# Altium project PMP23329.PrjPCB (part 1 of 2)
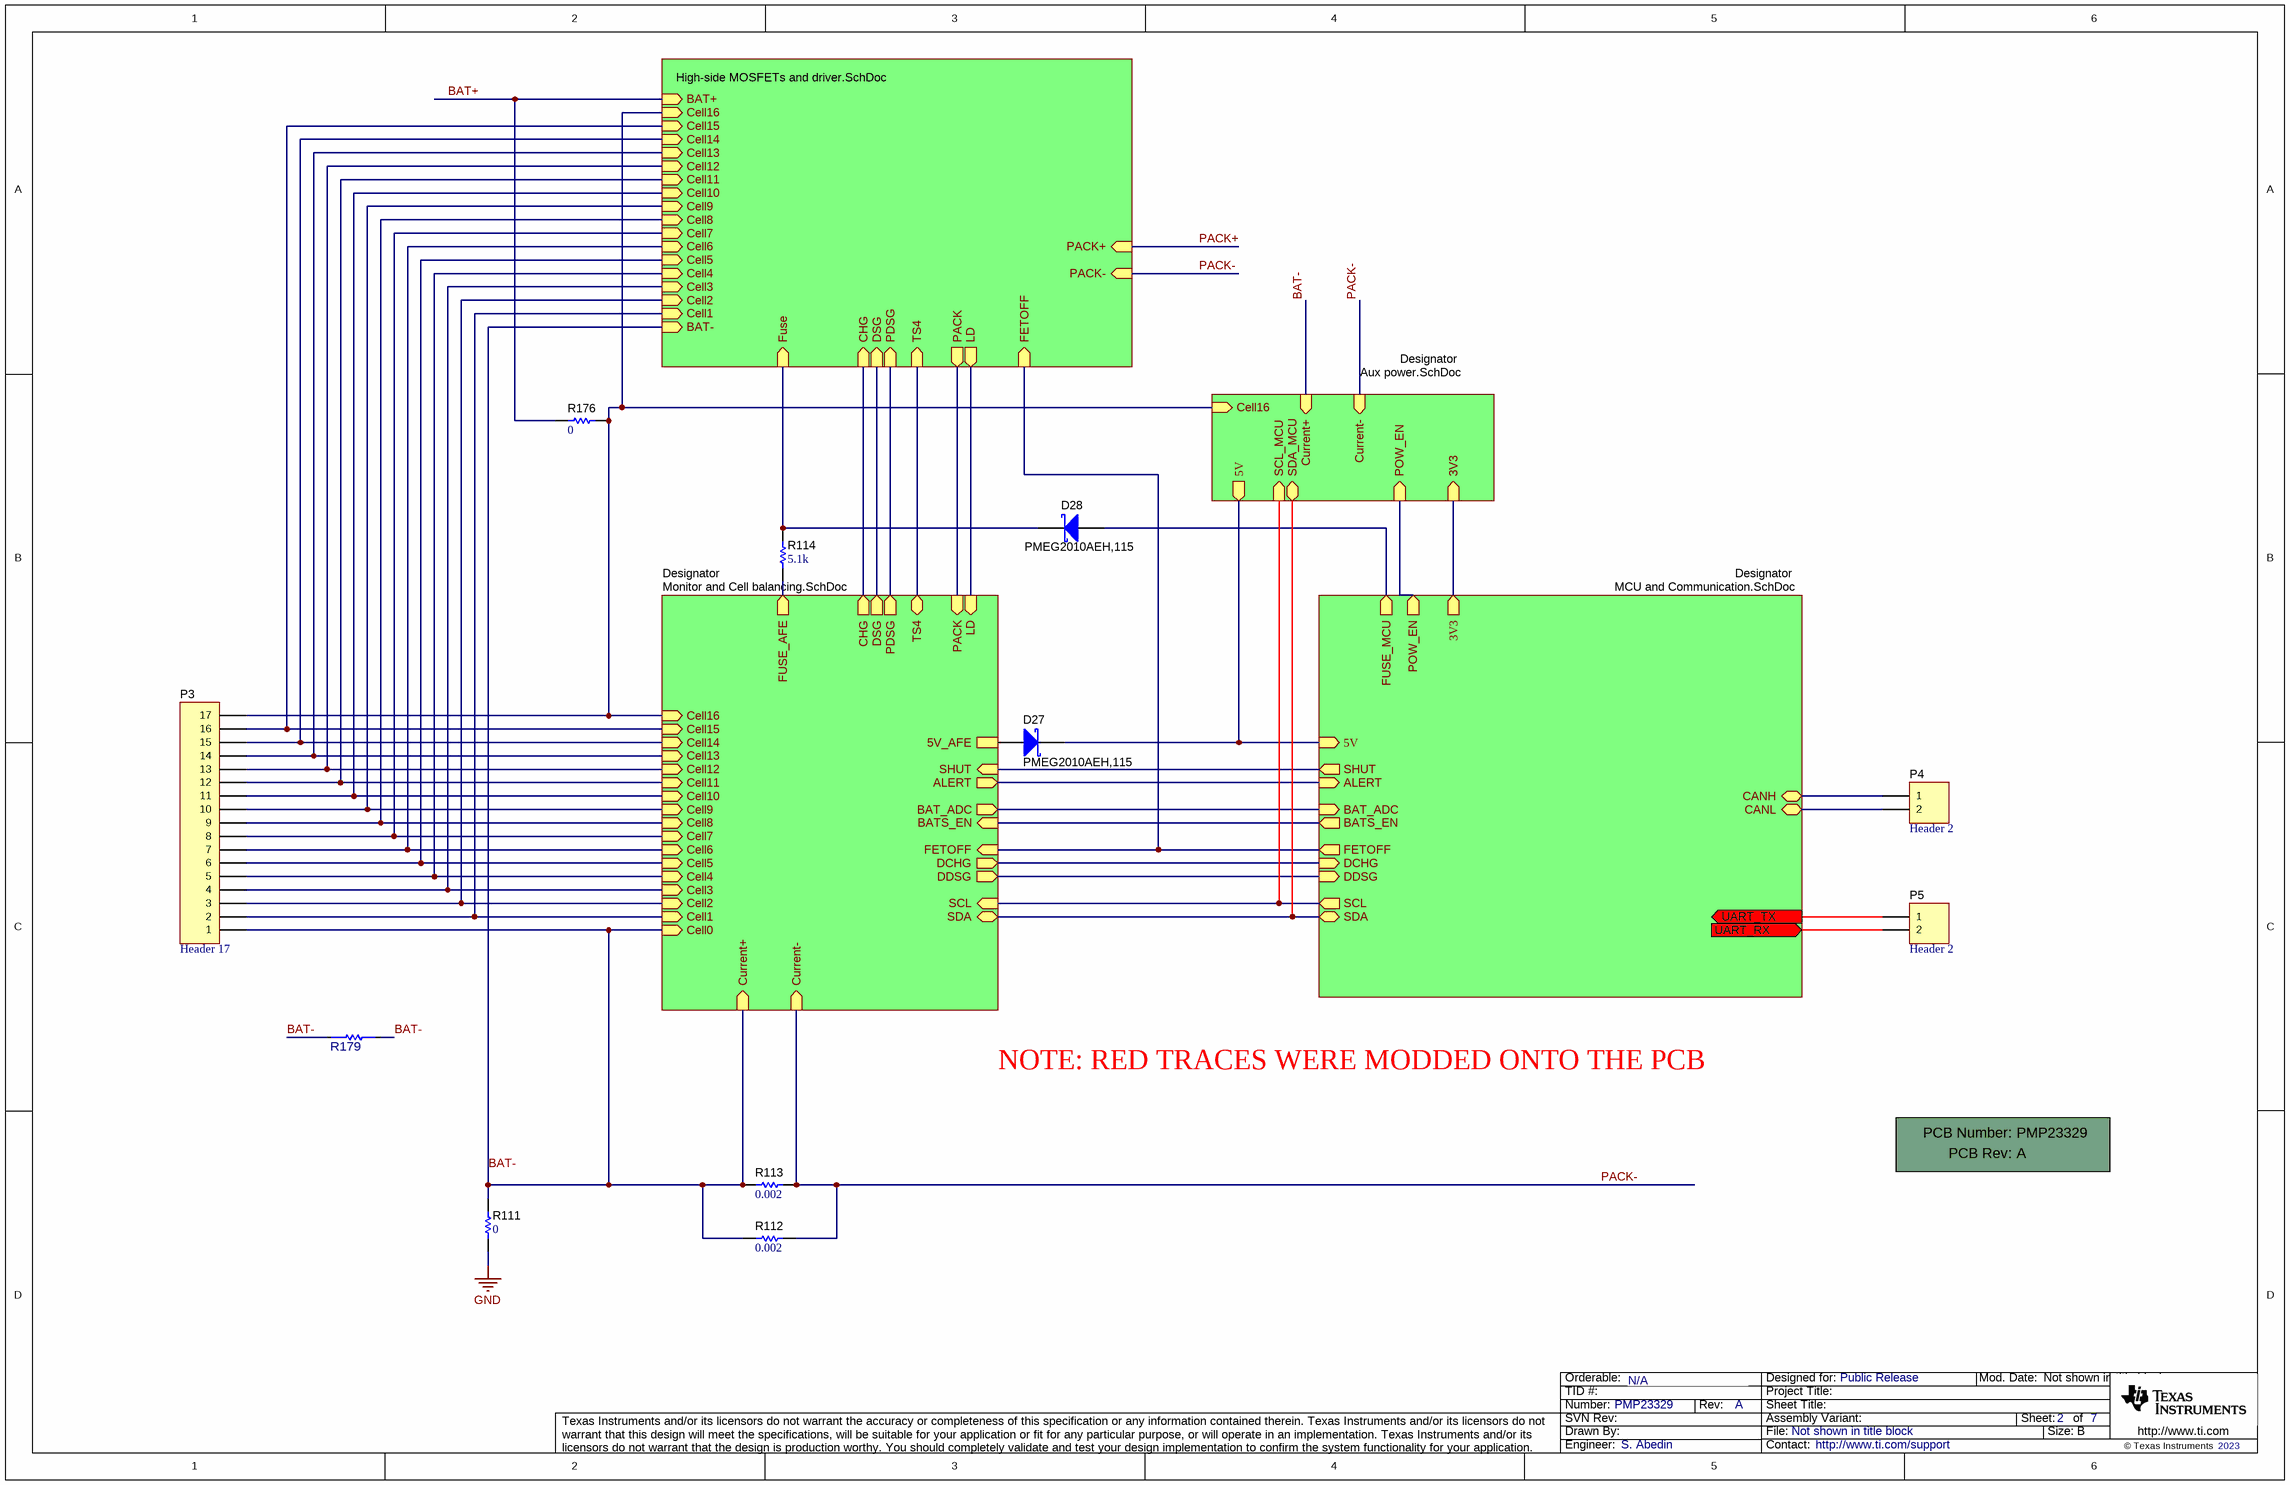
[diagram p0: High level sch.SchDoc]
CopyrightYear: 2023; PCB_Layout: S. Abedin; PCB_Rev: A; PRJ_Customer: Public Release; PRJ_Engineer: S. Abedin; PRJ_Number: PMP23329; SCH_Rev: A; TechSupport: http://www.ti.com/support
5 sheets, 381 parts. Net scope: hierarchical (ports join the sheet entries above them; power ports are global).
Board file: v1.PcbDoc
Sheets:
  High level sch.SchDoc
    Designator = Monitor and Cell balancing.SchDoc
    Designator = Aux power.SchDoc
    Designator = MCU and Communication.SchDoc
    Designator = High-side MOSFETs and driver.SchDoc

## Sheet High level sch.SchDoc
size 431 x 279 mm; Date: Not shown in title block; ApprovedBy: Not shown in title block; CheckedBy: Not shown in title block; Author: Not shown in title block; CompanyName: Not shown in title block; Engineer: Not shown in title block; Organization: Not shown in title block; Address1: Not shown in title block; Address2: Not shown in title block; Address3: Not shown in title block; Address4: Not shown in title block; DocumentNumber: 1; Revision: Use project parameter SCH_Rev; SheetNumber: 2; SheetTotal: 7; PageSetup: Record=PageOptions¦CenterHorizontal=True¦CenterVertical=True¦PrintScale=1.00¦XCorrection=1.00¦YCorrection=1.00¦PrintKind=0¦BorderSize=5000000¦LeftOffset=0¦BottomOffset=0¦Orientation=2¦PaperLength=1000¦PaperWidth=1000¦Scale=100¦PaperSource=15¦PrintQuality=600¦MediaType=1¦DitherType=10¦PaperKind=Letter¦PrintScaleMode=1

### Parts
!PCB1  Printed Circuit Board  (value not drawn)  (mechanical)
D27  PMEG2010AEH,115  [SOD-123F]
D28  PMEG2010AEH,115  [SOD-123F]
P3  Header 17  [HDR1X17]
P4  Header 2  [HDR1X2]
P5  Header 2  [HDR1X2]
R111  ValueDisplayed: 0  [1206]  (hidden comment: MCR18EZHJ000)
R112  ValueDisplayed: 0.002  [2512]  (hidden comment: CSNL2512FT2L00)
R113  ValueDisplayed: 0.002  [2512]  (hidden comment: CSNL2512FT2L00)
R114  ValueDisplayed: 5.1k  [0603S]  (hidden comment: CRCW06035K10JNEA)
R176  ValueDisplayed: 0  [2010]  (hidden comment: CRCW20100000Z0EF)
R179  RC2512FK-070RL  [FP-RC2512FK-070RL_2512-MFG]  (value not drawn)

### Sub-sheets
Designator = Monitor and Cell balancing.SchDoc: SHUT (in), ALERT (out), DDSG (out), DSG (out), DCHG (out), SCL (in), PDSG (out), Cell9 (in), SDA (bidir), CHG (out), Cell4 (in), Cell3 (in), Cell5 (in), Current+ (in), Current- (in), Cell8 (in), Cell12 (in), Cell6 (in), Cell7 (in), Cell10 (in), Cell11 (in), Cell2 (in), Cell1 (in), Cell15 (in), Cell16 (in), Cell0 (in), Cell13 (in), Cell14 (in), FETOFF (in), PACK (in), LD (in), 5V_AFE, FUSE_AFE (out), BAT_ADC (out), BATS_EN (in), TS4 (bidir)
Designator = Aux power.SchDoc: POW_EN (in), Cell16 (in), 5V (out), 3V3 (in), Current+ (in), Current- (in), SCL_MCU (in), SDA_MCU (bidir)
Designator = MCU and Communication.SchDoc: SDA (bidir), SCL (out), CANL (bidir), CANH (bidir), ALERT (in), POW_EN (out), DDSG (in), DCHG (in), SHUT (out), FETOFF (out), FUSE_MCU (out), BAT_ADC (in), BATS_EN (out), 5V (in), 3V3 (out)
Designator = High-side MOSFETs and driver.SchDoc: PACK- (in), CHG (in), DSG (in), Fuse (in), PACK+ (in), BAT+ (in), PACK (out), LD (out), PDSG (in), BAT- (in), Cell9 (in), Cell4 (in), Cell3 (in), Cell5 (in), Cell8 (in), Cell12 (in), Cell6 (in), Cell7 (in), Cell10 (in), Cell11 (in), Cell2 (in), Cell1 (in), Cell15 (in), Cell16 (in), Cell13 (in), Cell14 (in), FETOFF (in), TS4 (in)

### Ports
UART_RX (in), UART_TX (out)

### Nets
GND: R111.1
3V3: sheet Designator/3V3, sheet Designator/3V3
5V: D27.1(K) ; sheet Designator/5V, sheet Designator/5V
5V_AFE: D27.2(A) ; sheet Designator/5V_AFE
ALERT: sheet Designator/ALERT, sheet Designator/ALERT
BAT+: R176.1 ; sheet Designator/BAT+
BAT-: P3.1 R111.2 R112.1 R113.1 R179.1 R179.2 ; sheet Designator/Current+, sheet Designator/Cell0, sheet Designator/Current+, sheet Designator/BAT-
BAT_ADC: sheet Designator/BAT_ADC, sheet Designator/BAT_ADC
BATS_EN: sheet Designator/BATS_EN, sheet Designator/BATS_EN
CANH: P4.1 ; sheet Designator/CANH
CANL: P4.2 ; sheet Designator/CANL
Cell1: P3.2 ; sheet Designator/Cell1, sheet Designator/Cell1
Cell2: P3.3 ; sheet Designator/Cell2, sheet Designator/Cell2
Cell3: P3.4 ; sheet Designator/Cell3, sheet Designator/Cell3
Cell4: P3.5 ; sheet Designator/Cell4, sheet Designator/Cell4
Cell5: P3.6 ; sheet Designator/Cell5, sheet Designator/Cell5
Cell6: P3.7 ; sheet Designator/Cell6, sheet Designator/Cell6
Cell7: P3.8 ; sheet Designator/Cell7, sheet Designator/Cell7
Cell8: P3.9 ; sheet Designator/Cell8, sheet Designator/Cell8
Cell9: P3.10 ; sheet Designator/Cell9, sheet Designator/Cell9
Cell10: P3.11 ; sheet Designator/Cell10, sheet Designator/Cell10
Cell11: P3.12 ; sheet Designator/Cell11, sheet Designator/Cell11
Cell12: P3.13 ; sheet Designator/Cell12, sheet Designator/Cell12
Cell13: P3.14 ; sheet Designator/Cell13, sheet Designator/Cell13
Cell14: P3.15 ; sheet Designator/Cell14, sheet Designator/Cell14
Cell15: P3.16 ; sheet Designator/Cell15, sheet Designator/Cell15
Cell16: P3.17 R176.2 ; sheet Designator/Cell16, sheet Designator/Cell16, sheet Designator/Cell16
CHG: sheet Designator/CHG, sheet Designator/CHG
DCHG: sheet Designator/DCHG, sheet Designator/DCHG
DDSG: sheet Designator/DDSG, sheet Designator/DDSG
DSG: sheet Designator/DSG, sheet Designator/DSG
FETOFF: sheet Designator/FETOFF, sheet Designator/FETOFF, sheet Designator/FETOFF
Fuse: D28.1(K) R114.2 ; sheet Designator/Fuse
FUSE_AFE: R114.1 ; sheet Designator/FUSE_AFE
FUSE_MCU: D28.2(A) ; sheet Designator/FUSE_MCU
LD: sheet Designator/LD, sheet Designator/LD
PACK: sheet Designator/PACK, sheet Designator/PACK
PACK-: R112.2 R113.2 ; sheet Designator/Current-, sheet Designator/Current-, sheet Designator/PACK-
PDSG: sheet Designator/PDSG, sheet Designator/PDSG
POW_EN: sheet Designator/POW_EN, sheet Designator/POW_EN
SCL_MCU: sheet Designator/SCL, sheet Designator/SCL_MCU, sheet Designator/SCL
SDA_MCU: sheet Designator/SDA, sheet Designator/SDA_MCU, sheet Designator/SDA
SHUT: sheet Designator/SHUT, sheet Designator/SHUT
TS4: sheet Designator/TS4, sheet Designator/TS4
UART_RX: P5.2 ; port UART_RX
UART_TX: P5.1 ; port UART_TX

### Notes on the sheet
- NOTE: RED TRACES WERE MODDED ONTO THE PCB
- N/A

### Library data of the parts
!PCB1 = CMP-0003618-2: Manufacturer: Any; PartNumber: PMP23329
D27 D28 = CMP-0077033-2: Diode, Schottky, 20 V, 1 A, SOD-123F; Manufacturer: Nexperia; Vf_V: 430mV; Value: 20V; Value1: 1A; Value2: 0.43V; TJmax_C: 150°C; SizeAreaWB_mm2: 11.7; SizeArea_mm2: 5.6; SizeX_mm: 3.5; SizeY_mm: 1.6; SizeZ_mm: 1.1; AEC Category: Q101; Green_Lifecycle: Not Set; Green_REACh: Incomplete
P3 = Header 17: Header, 17-Pin
P4 P5 = Header 2: Header, 2-Pin
R111 = CMP-0018756-3: RES, 0, 5%, 0.25 W, 1206; Manufacturer: Rohm; SizeZ_mm: 1.35; SizeY_mm: 1.6; Value_Code: 0000; TempCo: 200 ppm/C; SizeArea_mm2: 5.12; U/M: EA; EIA_Code: E24; Value2: 0.25W; AEC Category: Q200; MFG_Status: TI_Obsolete; Value: 0; SizeX_mm: 3.2; VDC_V: 200V; Power_W: 250mW
R112 R113 = CMP-0015756-2: RES, 0.002, 1%, 2 W, 2512; Manufacturer: Stackpole Electronics Inc; Value: 0.002; Res_ohm: 2m; Value_Code: 2L000; Power_W: 2W; VDC_V: 200V; TempCo: 50 ppm/C; SizeArea_mm2: 20.16; SizeX_mm: 6.3; SizeY_mm: 3.2; SizeZ_mm: 0.71; U/M: EA; AEC Category: Q200
R114 = CMP-0025830-4: RES, 5.1 k, 5%, 0.1 W, AEC-Q200 Grade 0, 0603; Manufacturer: Vishay-Dale; Value: 5.1k; Value_Code: 5k10; Power_W: 100mW; Value2: 0.1W; VDC_V: 75V; TempCo: 200 ppm/C; SizeArea_mm2: 1.28; SizeX_mm: 1.6; SizeY_mm: 0.8; SizeZ_mm: 1; EIA_Code: E24; AEC Category: Q200; AEC Qualified: Y; AEC Grade: 0
R176 = CMP-0016044-2: RES, 0, 5%, 0.75 W, AEC-Q200 Grade 0, 2010; Manufacturer: Vishay-Dale; Power_W: 750mW; TempCo: ppm/C; Value_Code: 0000; U/M: EA; Value: 0; EIA_Code: E24; SizeX_mm: 5; SizeY_mm: 2.5; SizeZ_mm: 1.66; Value2: 0.75W; SizeArea_mm2: 12.5; AEC Qualified: Y; AEC Category: Q200
R179 = CMP-0096746-1: 0 Ohms Jumper 1W Chip Resistor 2512 (6432 Metric) Moisture Resistant Thick Film; Manufacturer: YAGEO; Value: 0; AEC Qualified: No; VDC_V: 200V; SizeZ_mm: 0.65mm; Max Current: 10A

## Sheet Monitor and Cell balancing.SchDoc
size A3; Date: Not shown in title block; ApprovedBy: Not shown in title block; CheckedBy: Not shown in title block; Author: Not shown in title block; CompanyName: Not shown in title block; Engineer: Not shown in title block; Organization: Not shown in title block; Address1: Not shown in title block; Address2: Not shown in title block; Address3: Not shown in title block; Address4: Not shown in title block; DocumentNumber: 1; Revision: Use project parameter SCH_Rev; SheetNumber: 3; SheetTotal: 7; PageSetup: Record=PageOptions¦CenterHorizontal=True¦CenterVertical=True¦PrintScale=1.00¦XCorrection=1.00¦YCorrection=1.00¦PrintKind=0¦BorderSize=5000000¦LeftOffset=0¦BottomOffset=0¦Orientation=2¦PaperLength=1000¦PaperWidth=1000¦Scale=100¦PaperSource=15¦PrintQuality=600¦MediaType=1¦DitherType=10¦PaperKind=Letter¦PrintScaleMode=1
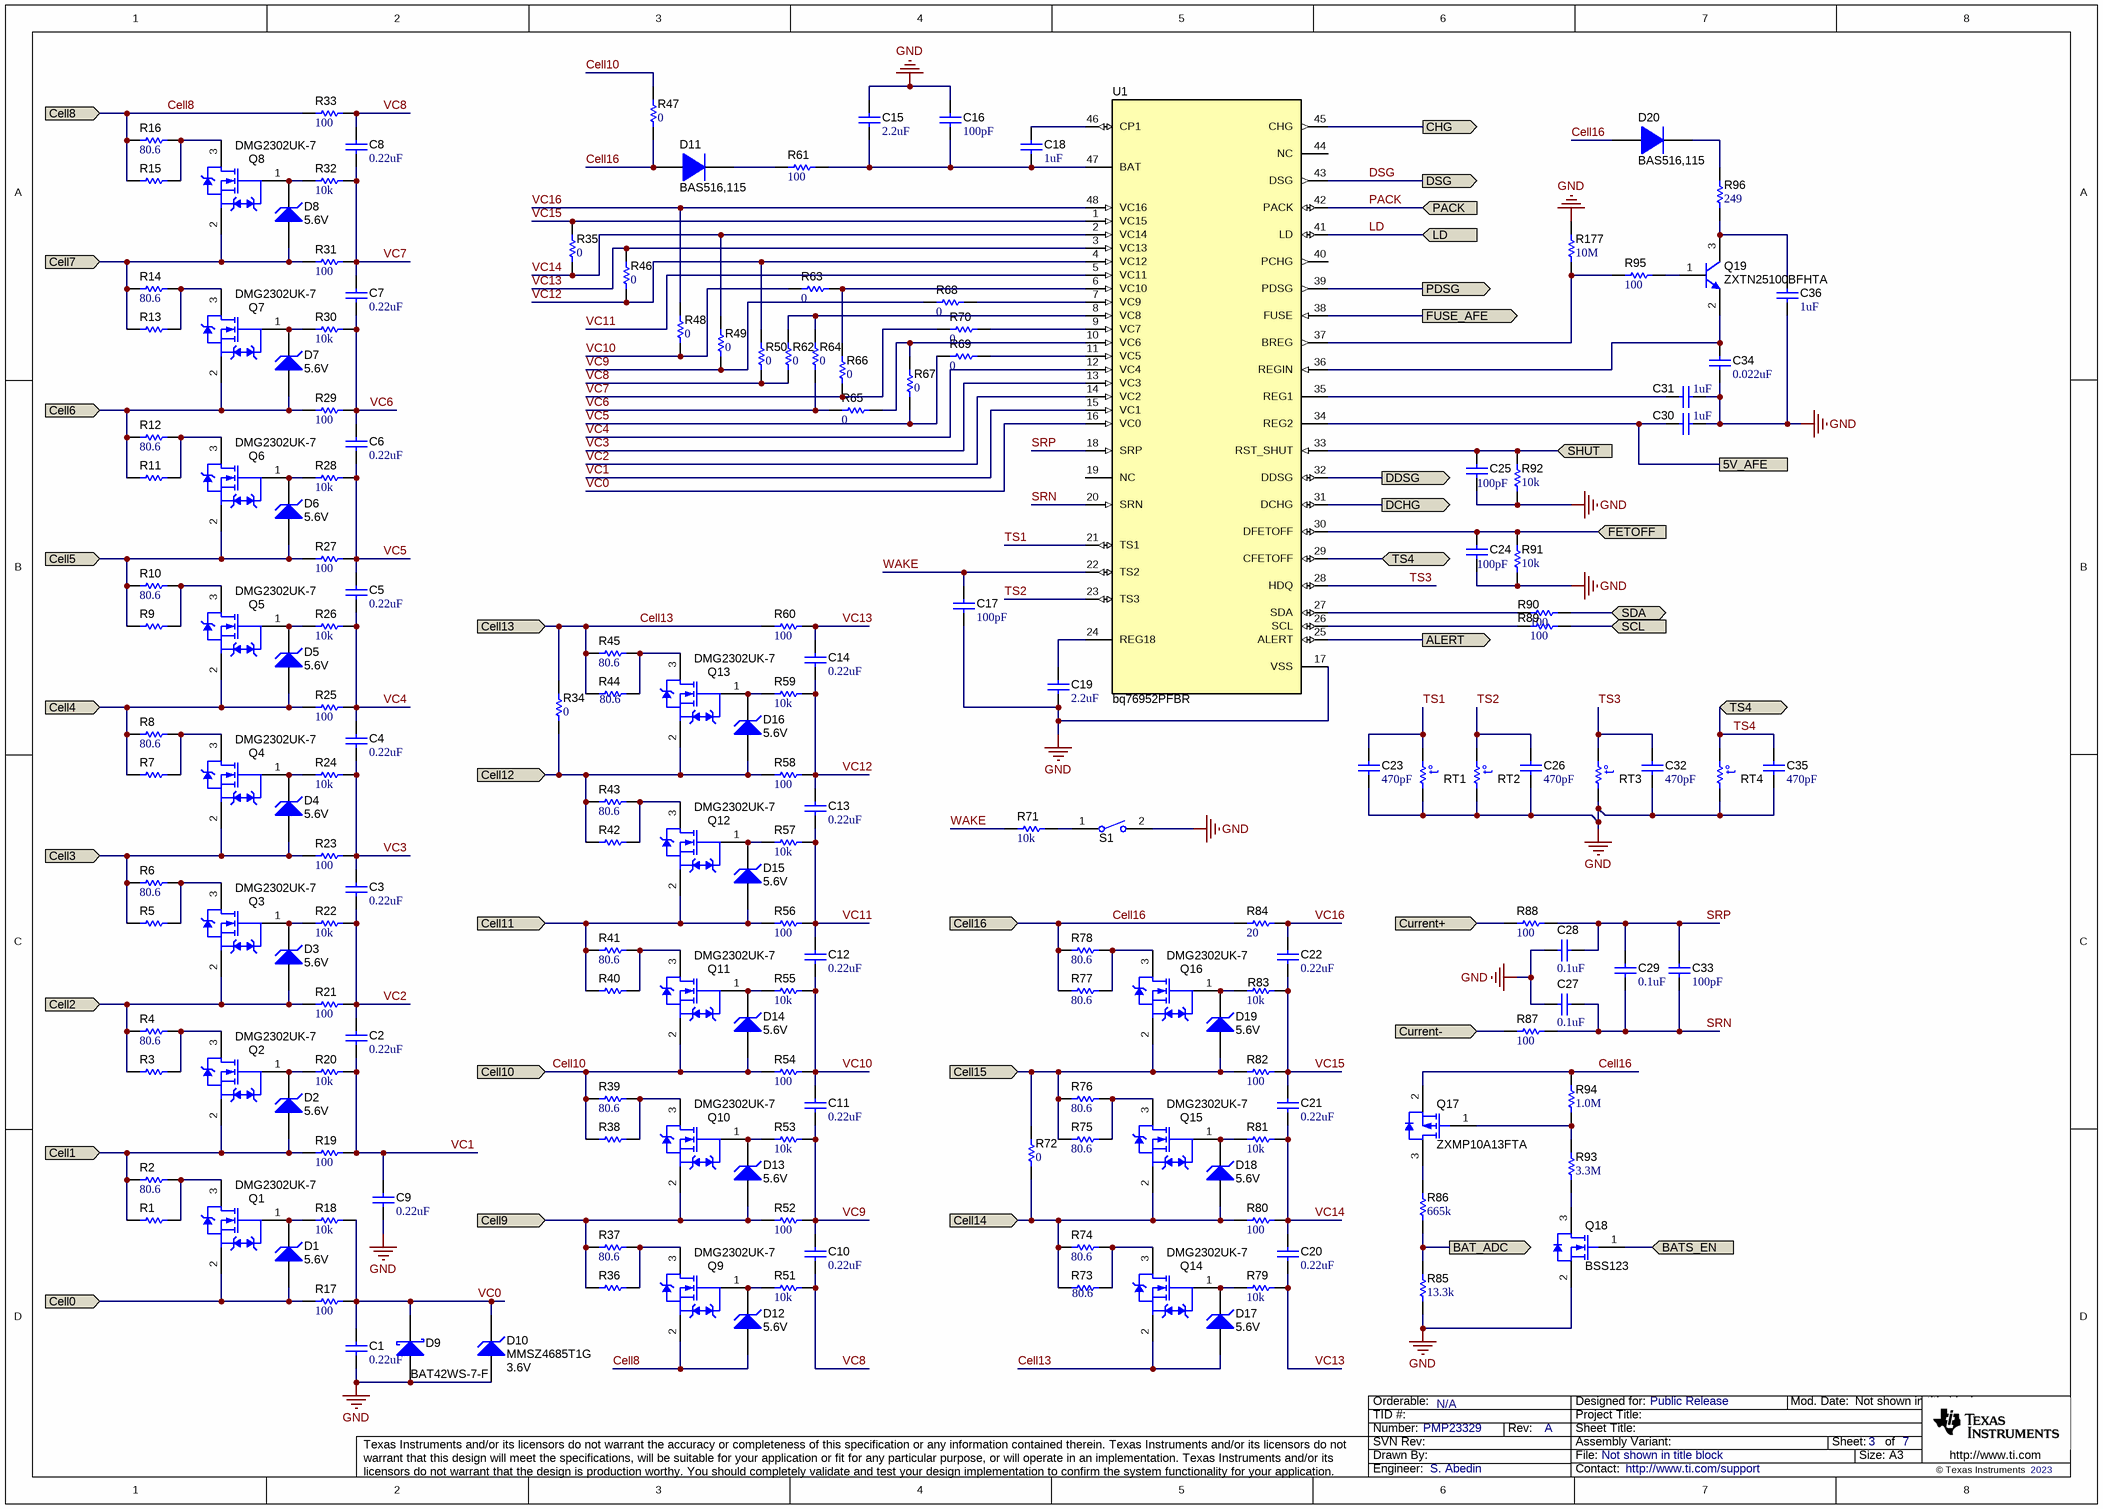
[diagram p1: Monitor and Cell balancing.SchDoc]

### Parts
C1  ValueDisplayed: 0.22uF  [0603S]  (hidden comment: GCM188R71H224KA64D)
C2  ValueDisplayed: 0.22uF  [0603S]  (hidden comment: GCM188R71H224KA64D)
C3  ValueDisplayed: 0.22uF  [0603S]  (hidden comment: GCM188R71H224KA64D)
C4  ValueDisplayed: 0.22uF  [0603S]  (hidden comment: GCM188R71H224KA64D)
C5  ValueDisplayed: 0.22uF  [0603S]  (hidden comment: GCM188R71H224KA64D)
C6  ValueDisplayed: 0.22uF  [0603S]  (hidden comment: GCM188R71H224KA64D)
C7  ValueDisplayed: 0.22uF  [0603S]  (hidden comment: GCM188R71H224KA64D)
C8  ValueDisplayed: 0.22uF  [0603S]  (hidden comment: GCM188R71H224KA64D)
C9  ValueDisplayed: 0.22uF  [0603S]  (hidden comment: GCM188R71H224KA64D)
C10  ValueDisplayed: 0.22uF  [0603S]  (hidden comment: GCM188R71H224KA64D)
C11  ValueDisplayed: 0.22uF  [0603S]  (hidden comment: GCM188R71H224KA64D)
C12  ValueDisplayed: 0.22uF  [0603S]  (hidden comment: GCM188R71H224KA64D)
C13  ValueDisplayed: 0.22uF  [0603S]  (hidden comment: GCM188R71H224KA64D)
C14  ValueDisplayed: 0.22uF  [0603S]  (hidden comment: GCM188R71H224KA64D)
C15  ValueDisplayed: 2.2uF  [1206_190]  (hidden comment: CL31B225KCHSNNE)
C16  ValueDisplayed: 100pF  [0603S]  (hidden comment: GRM1885C2A101JA01D)
C17  ValueDisplayed: 100pF  [0603S]  (hidden comment: GRM1885C2A101JA01D)
C18  ValueDisplayed: 1uF  [0603S]  (hidden comment: C1608X7R1E105K080AB)
C19  ValueDisplayed: 2.2uF  [0603S]  (hidden comment: EMK107BB7225MA-T)
C20  ValueDisplayed: 0.22uF  [0603S]  (hidden comment: GCM188R71H224KA64D)
C21  ValueDisplayed: 0.22uF  [0603S]  (hidden comment: GCM188R71H224KA64D)
C22  ValueDisplayed: 0.22uF  [0603S]  (hidden comment: GCM188R71H224KA64D)
C23  ValueDisplayed: 470pF  [0603S]  (hidden comment: GRM188R71H471KA01D)
C24  ValueDisplayed: 100pF  [0603S]  (hidden comment: GRM1885C2A101JA01D)
C25  ValueDisplayed: 100pF  [0603S]  (hidden comment: GRM1885C2A101JA01D)
C26  ValueDisplayed: 470pF  [0603S]  (hidden comment: GRM188R71H471KA01D)
C27  ValueDisplayed: 0.1uF  [0603S]  (hidden comment: GRM188R71H104KA93D)
C28  ValueDisplayed: 0.1uF  [0603S]  (hidden comment: GRM188R71H104KA93D)
C29  ValueDisplayed: 0.1uF  [0603S]  (hidden comment: GRM188R71H104KA93D)
C30  ValueDisplayed: 1uF  [0603S]  (hidden comment: GCM188R71C105KA64D)
C31  ValueDisplayed: 1uF  [0603S]  (hidden comment: GCM188R71C105KA64D)
C32  ValueDisplayed: 470pF  [0603S]  (hidden comment: GRM188R71H471KA01D)
C33  ValueDisplayed: 100pF  [0603S]  (hidden comment: GRM1885C2A101JA01D)
C34  ValueDisplayed: 0.022uF  [0603S]  (hidden comment: GRM188R71H223KA01D)
C35  ValueDisplayed: 470pF  [0603S]  (hidden comment: GRM188R71H471KA01D)
C36  ValueDisplayed: 1uF  [1206_180]  (hidden comment: C3216X7R2A105K160AA)
D1  value 5.6V  [SOD-523]  (hidden comment: BZT52C5V6T-7)
D2  value 5.6V  [SOD-523]  (hidden comment: BZT52C5V6T-7)
D3  value 5.6V  [SOD-523]  (hidden comment: BZT52C5V6T-7)
D4  value 5.6V  [SOD-523]  (hidden comment: BZT52C5V6T-7)
D5  value 5.6V  [SOD-523]  (hidden comment: BZT52C5V6T-7)
D6  value 5.6V  [SOD-523]  (hidden comment: BZT52C5V6T-7)
D7  value 5.6V  [SOD-523]  (hidden comment: BZT52C5V6T-7)
D8  value 5.6V  [SOD-523]  (hidden comment: BZT52C5V6T-7)
D9  BAT42WS-7-F  [SOD-323]
D10  MMSZ4685T1G  value 3.6V  [SOD-123]
D11  BAS516,115  [SOD-523]
D12  value 5.6V  [SOD-523]  (hidden comment: BZT52C5V6T-7)
D13  value 5.6V  [SOD-523]  (hidden comment: BZT52C5V6T-7)
D14  value 5.6V  [SOD-523]  (hidden comment: BZT52C5V6T-7)
D15  value 5.6V  [SOD-523]  (hidden comment: BZT52C5V6T-7)
D16  value 5.6V  [SOD-523]  (hidden comment: BZT52C5V6T-7)
D17  value 5.6V  [SOD-523]  (hidden comment: BZT52C5V6T-7)
D18  value 5.6V  [SOD-523]  (hidden comment: BZT52C5V6T-7)
D19  value 5.6V  [SOD-523]  (hidden comment: BZT52C5V6T-7)
D20  BAS516,115  [SOD-523]
Q1  DMG2302UK-7  [SOT-23]
Q2  DMG2302UK-7  [SOT-23]
Q3  DMG2302UK-7  [SOT-23]
Q4  DMG2302UK-7  [SOT-23]
Q5  DMG2302UK-7  [SOT-23]
Q6  DMG2302UK-7  [SOT-23]
Q7  DMG2302UK-7  [SOT-23]
Q8  DMG2302UK-7  [SOT-23]
Q9  DMG2302UK-7  [SOT-23]
Q10  DMG2302UK-7  [SOT-23]
Q11  DMG2302UK-7  [SOT-23]
Q12  DMG2302UK-7  [SOT-23]
Q13  DMG2302UK-7  [SOT-23]
Q14  DMG2302UK-7  [SOT-23]
Q15  DMG2302UK-7  [SOT-23]
Q16  DMG2302UK-7  [SOT-23]
Q17  ZXMP10A13FTA  [SOT-23]
Q18  BSS123  [SOT-23]
Q19  ZXTN25100BFHTA  [SOT-23]
R1  CRCW120680R6FKEA  [1206]  (value not drawn)
R2  ValueDisplayed: 80.6  [1206]  (hidden comment: CRCW120680R6FKEA)
R3  CRCW120680R6FKEA  [1206]  (value not drawn)
R4  ValueDisplayed: 80.6  [1206]  (hidden comment: CRCW120680R6FKEA)
R5  CRCW120680R6FKEA  [1206]  (value not drawn)
R6  ValueDisplayed: 80.6  [1206]  (hidden comment: CRCW120680R6FKEA)
R7  CRCW120680R6FKEA  [1206]  (value not drawn)
R8  ValueDisplayed: 80.6  [1206]  (hidden comment: CRCW120680R6FKEA)
R9  CRCW120680R6FKEA  [1206]  (value not drawn)
R10  ValueDisplayed: 80.6  [1206]  (hidden comment: CRCW120680R6FKEA)
R11  CRCW120680R6FKEA  [1206]  (value not drawn)
R12  ValueDisplayed: 80.6  [1206]  (hidden comment: CRCW120680R6FKEA)
R13  CRCW120680R6FKEA  [1206]  (value not drawn)
R14  ValueDisplayed: 80.6  [1206]  (hidden comment: CRCW120680R6FKEA)
R15  CRCW120680R6FKEA  [1206]  (value not drawn)
R16  ValueDisplayed: 80.6  [1206]  (hidden comment: CRCW120680R6FKEA)
R17  ValueDisplayed: 100  [0603S]  (hidden comment: CRCW0603100RFKEA)
R18  ValueDisplayed: 10k  [0603S]  (hidden comment: CRCW060310K0JNEA)
R19  ValueDisplayed: 100  [0603S]  (hidden comment: CRCW0603100RFKEA)
R20  ValueDisplayed: 10k  [0603S]  (hidden comment: CRCW060310K0JNEA)
R21  ValueDisplayed: 100  [0603S]  (hidden comment: CRCW0603100RFKEA)
R22  ValueDisplayed: 10k  [0603S]  (hidden comment: CRCW060310K0JNEA)
R23  ValueDisplayed: 100  [0603S]  (hidden comment: CRCW0603100RFKEA)
R24  ValueDisplayed: 10k  [0603S]  (hidden comment: CRCW060310K0JNEA)
R25  ValueDisplayed: 100  [0603S]  (hidden comment: CRCW0603100RFKEA)
R26  ValueDisplayed: 10k  [0603S]  (hidden comment: CRCW060310K0JNEA)
R27  ValueDisplayed: 100  [0603S]  (hidden comment: CRCW0603100RFKEA)
R28  ValueDisplayed: 10k  [0603S]  (hidden comment: CRCW060310K0JNEA)
R29  ValueDisplayed: 100  [0603S]  (hidden comment: CRCW0603100RFKEA)
R30  ValueDisplayed: 10k  [0603S]  (hidden comment: CRCW060310K0JNEA)
R31  ValueDisplayed: 100  [0603S]  (hidden comment: CRCW0603100RFKEA)
R32  ValueDisplayed: 10k  [0603S]  (hidden comment: CRCW060310K0JNEA)
R33  ValueDisplayed: 100  [0603S]  (hidden comment: CRCW0603100RFKEA)
R34  ValueDisplayed: 0  [0402]  (hidden comment: CRCW04020000Z0ED)
R35  ValueDisplayed: 0  [0603S]  (hidden comment: CRCW06030000Z0EA)
R36  CRCW120680R6FKEA  [1206]  (value not drawn)
R37  ValueDisplayed: 80.6  [1206]  (hidden comment: CRCW120680R6FKEA)
R38  CRCW120680R6FKEA  [1206]  (value not drawn)
R39  ValueDisplayed: 80.6  [1206]  (hidden comment: CRCW120680R6FKEA)
R40  CRCW120680R6FKEA  [1206]  (value not drawn)
R41  ValueDisplayed: 80.6  [1206]  (hidden comment: CRCW120680R6FKEA)
R42  CRCW120680R6FKEA  [1206]  (value not drawn)
R43  ValueDisplayed: 80.6  [1206]  (hidden comment: CRCW120680R6FKEA)
R44  value 80.6  [1206]  (hidden comment: CRCW120680R6FKEA)
R45  ValueDisplayed: 80.6  [1206]  (hidden comment: CRCW120680R6FKEA)
R46  ValueDisplayed: 0  [0402]  (hidden comment: CRCW04020000Z0ED)
R47  ValueDisplayed: 0  [0402]  (hidden comment: CRCW04020000Z0ED)
R48  ValueDisplayed: 0  [0603S]  (hidden comment: CRCW06030000Z0EA)
R49  ValueDisplayed: 0  [0603S]  (hidden comment: CRCW06030000Z0EA)
R50  ValueDisplayed: 0  [0603S]  (hidden comment: CRCW06030000Z0EA)
R51  ValueDisplayed: 10k  [0603S]  (hidden comment: CRCW060310K0JNEA)
R52  ValueDisplayed: 100  [0603S]  (hidden comment: CRCW0603100RFKEA)
R53  ValueDisplayed: 10k  [0603S]  (hidden comment: CRCW060310K0JNEA)
R54  ValueDisplayed: 100  [0603S]  (hidden comment: CRCW0603100RFKEA)
R55  ValueDisplayed: 10k  [0603S]  (hidden comment: CRCW060310K0JNEA)
R56  ValueDisplayed: 100  [0603S]  (hidden comment: CRCW0603100RFKEA)
R57  ValueDisplayed: 10k  [0603S]  (hidden comment: CRCW060310K0JNEA)
R58  ValueDisplayed: 100  [0603S]  (hidden comment: CRCW0603100RFKEA)
R59  ValueDisplayed: 10k  [0603S]  (hidden comment: CRCW060310K0JNEA)
R60  ValueDisplayed: 100  [0603S]  (hidden comment: CRCW0603100RFKEA)
R61  ValueDisplayed: 100  [0603S]  (hidden comment: CRCW0603100RFKEA)
R62  ValueDisplayed: 0  [0603S]  (hidden comment: CRCW06030000Z0EA)
R63  ValueDisplayed: 0  [0603S]  (hidden comment: CRCW06030000Z0EA)
R64  ValueDisplayed: 0  [0603S]  (hidden comment: CRCW06030000Z0EA)
R65  ValueDisplayed: 0  [0603S]  (hidden comment: CRCW06030000Z0EA)
R66  ValueDisplayed: 0  [0603S]  (hidden comment: CRCW06030000Z0EA)
R67  ValueDisplayed: 0  [0603S]  (hidden comment: CRCW06030000Z0EA)
R68  ValueDisplayed: 0  [0603S]  (hidden comment: CRCW06030000Z0EA)
R69  ValueDisplayed: 0  [0603S]  (hidden comment: CRCW06030000Z0EA)
R70  ValueDisplayed: 0  [0603S]  (hidden comment: CRCW06030000Z0EA)
R71  ValueDisplayed: 10k  [0603S]  (hidden comment: CRCW060310K0JNEA)
R72  ValueDisplayed: 0  [0402]  (hidden comment: CRCW04020000Z0ED)
R73  ValueDisplayed: 80.6  [1206]  (hidden comment: CRCW120680R6FKEA)
R74  ValueDisplayed: 80.6  [1206]  (hidden comment: CRCW120680R6FKEA)
R75  ValueDisplayed: 80.6  [1206]  (hidden comment: CRCW120680R6FKEA)
R76  ValueDisplayed: 80.6  [1206]  (hidden comment: CRCW120680R6FKEA)
R77  ValueDisplayed: 80.6  [1206]  (hidden comment: CRCW120680R6FKEA)
R78  ValueDisplayed: 80.6  [1206]  (hidden comment: CRCW120680R6FKEA)
R79  ValueDisplayed: 10k  [0603S]  (hidden comment: CRCW060310K0JNEA)
R80  ValueDisplayed: 100  [0603S]  (hidden comment: CRCW0603100RFKEA)
R81  ValueDisplayed: 10k  [0603S]  (hidden comment: CRCW060310K0JNEA)
R82  ValueDisplayed: 100  [0603S]  (hidden comment: CRCW0603100RFKEA)
R83  ValueDisplayed: 10k  [0603S]  (hidden comment: CRCW060310K0JNEA)
R84  ValueDisplayed: 20  [0603S]  (hidden comment: CRCW060320R0JNEA)
R85  ValueDisplayed: 13.3k  [0603S]  (hidden comment: RT0603DRE0713K3L)
R86  ValueDisplayed: 665k  [0603S]  (hidden comment: RT0603DRE07665KL)
R87  ValueDisplayed: 100  [0603S]  (hidden comment: CRCW0603100RFKEA)
R88  ValueDisplayed: 100  [0603S]  (hidden comment: CRCW0603100RFKEA)
R89  ValueDisplayed: 100  [0603S]  (hidden comment: CRCW0603100RFKEA)
R90  ValueDisplayed: 100  [0603S]  (hidden comment: CRCW0603100RFKEA)
R91  ValueDisplayed: 10k  [0603S]  (hidden comment: CRCW060310K0JNEA)
R92  ValueDisplayed: 10k  [0603S]  (hidden comment: CRCW060310K0JNEA)
R93  ValueDisplayed: 3.3M  [0603S]  (hidden comment: CRCW06033M30JNEA)
R94  ValueDisplayed: 1.0M  [0603S]  (hidden comment: CRCW06031M00JNEA)
R95  ValueDisplayed: 100  [0603S]  (hidden comment: CRCW0603100RFKEA)
R96  ValueDisplayed: 249  [0603S]  (hidden comment: RC0603FR-07249RL)
R177  ValueDisplayed: 10M  [0603S]  (hidden comment: CRCW060310M0JNEA)
RT1  MF51E103F3950  [Thermistor_103AT-2]  (value not drawn)
RT2  MF51E103F3950  [Thermistor_103AT-2]  (value not drawn)
RT3  MF51E103F3950  [Thermistor_103AT-2]  (value not drawn)
RT4  MF51E103F3950  [Thermistor_103AT-2]  (value not drawn)
S1  RS-032G05A3-SM RT  [SW_RS-032G05A3-SM]  (value not drawn)
U1  bq76952PFBR  [PFB0048A_N]

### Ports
5V_AFE, ALERT (out), BAT_ADC (out), BATS_EN (in), Cell0 (in), Cell1 (in), Cell2 (in), Cell3 (in), Cell4 (in), Cell5 (in), Cell6 (in), Cell7 (in), Cell8 (in), Cell9 (in), Cell10 (in), Cell11 (in), Cell12 (in), Cell13 (in), Cell14 (in), Cell15 (in), Cell16 (in), CHG (out), Current+ (in), Current- (in), DCHG (out), DDSG (out), DSG (out), FETOFF (in), FUSE_AFE (out), LD (in), PACK (in), PDSG (out), SCL (in), SDA (bidir), SHUT (in), TS4 (bidir)

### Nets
GND: C1.2 C9.2 C15.1 C16.1 C17.2 C19.2 C23.2 C24.2 C25.2 C26.2 C27.1 C28.1 C30.2 C31.2 C32.2 C34.2 C35.2 C36.2 D9.2(A) D10.2(A) Q18.2(S) R85.1 R91.1 R92.1 R177.2 RT1.1 RT2.1 RT3.1 RT4.1 S1.2 U1.17(VSS)
5V_AFE: C30.1 U1.34(REG2) ; port 5V_AFE
ALERT: U1.25(ALERT) ; port ALERT
BAT-: D1.2(A) Q1.2(S) R17.1 R88.1 ; port Cell0, port Current+
BAT_ADC: R85.2 R86.1 ; port BAT_ADC
BATS_EN: Q18.1(G) ; port BATS_EN
Cell1: D2.2(A) Q2.2(S) R1.1 R2.1 R19.1 ; port Cell1
Cell2: D3.2(A) Q3.2(S) R3.1 R4.1 R21.1 ; port Cell2
Cell3: D4.2(A) Q4.2(S) R5.1 R6.1 R23.1 ; port Cell3
Cell4: D5.2(A) Q5.2(S) R7.1 R8.1 R25.1 ; port Cell4
Cell5: D6.2(A) Q6.2(S) R9.1 R10.1 R27.1 ; port Cell5
Cell6: D7.2(A) Q7.2(S) R11.1 R12.1 R29.1 ; port Cell6
Cell7: D8.2(A) Q8.2(S) R13.1 R14.1 R31.1 ; port Cell7
Cell8: D12.2(A) Q9.2(S) R15.1 R16.1 R33.1 ; port Cell8
Cell9: D13.2(A) Q10.2(S) R36.1 R37.1 R52.1 ; port Cell9
Cell10: D14.2(A) Q11.2(S) R38.1 R39.1 R47.2 R54.1 ; port Cell10
Cell11: D15.2(A) Q12.2(S) R40.1 R41.1 R56.1 ; port Cell11
Cell12: D16.2(A) Q13.2(S) R34.1 R42.1 R43.1 R58.1 ; port Cell12
Cell13: D17.2(A) Q14.2(S) R34.2 R44.1 R45.1 R60.1 ; port Cell13
Cell14: D18.2(A) Q15.2(S) R72.1 R73.1 R74.1 R80.1 ; port Cell14
Cell15: D19.2(A) Q16.2(S) R72.2 R75.1 R76.1 R82.1 ; port Cell15
Cell16: D11.2(A) D20.2(A) Q17.2(S) R47.1 R77.1 R78.1 R84.1 R94.2 ; port Cell16
CHG: U1.45(CHG) ; port CHG
DCHG: U1.31(DCHG) ; port DCHG
DDSG: U1.32(DDSG) ; port DDSG
DSG: U1.43(DSG) ; port DSG
FETOFF: C24.1 R91.2 U1.30(DFETOFF) ; port FETOFF
FUSE_AFE: U1.38(FUSE) ; port FUSE_AFE
LD: U1.41(LD) ; port LD
PACK: U1.42(PACK) ; port PACK
PACK-: R87.1 ; port Current-
PDSG: U1.39(PDSG) ; port PDSG
SCL_MCU: R89.1 ; port SCL
SDA_MCU: R90.1 ; port SDA
SHUT: C25.1 R92.2 U1.33(RST_SHUT) ; port SHUT
SRN: C27.2 C29.2 C33.2 R87.2 U1.20(SRN)
SRP: C28.2 C29.1 C33.1 R88.2 U1.18(SRP)
TS1: C23.1 RT1.2 U1.21(TS1)
TS2: C26.1 RT2.2 U1.23(TS3)
TS3: C32.1 RT3.2 U1.28(HDQ)
TS4: C35.1 RT4.2 U1.29(CFETOFF) ; port TS4
VC0: C1.1 D9.1(K) D10.1(K) R17.2 R18.2 U1.16(VC0)
VC1: C2.2 C9.1 R19.2 R20.2 U1.15(VC1)
VC2: C2.1 C3.2 R21.2 R22.2 U1.14(VC2)
VC3: C3.1 C4.2 R23.2 R24.2 U1.13(VC3)
VC4: C4.1 C5.2 R25.2 R26.2 U1.12(VC4)
VC5: C5.1 C6.2 R27.2 R28.2 R67.1 R69.2
VC6: C6.1 C7.2 R29.2 R30.2 R64.1 R65.2
VC7: C7.1 C8.2 R31.2 R32.2 R66.1 R70.2
VC8: C8.1 C10.2 R33.2 R50.1 R51.2 R62.1
VC9: C10.1 C11.2 R49.1 R52.2 R53.2 R68.2
VC10: C11.1 C12.2 R48.1 R54.2 R55.2 R63.1
VC11: C12.1 C13.2 R56.2 R57.2 U1.5(VC11)
VC12: C13.1 C14.2 R46.1 R50.2 R58.2 R59.2 U1.4(VC12)
VC13: C14.1 C20.2 R46.2 R60.2 R79.2 U1.3(VC13)
VC14: C20.1 C21.2 R35.2 R49.2 R80.2 R81.2 U1.2(VC14)
VC15: C21.1 C22.2 R35.1 R82.2 R83.2 U1.1(VC15)
VC16: C22.1 R48.2 R84.2 U1.48(VC16)
WAKE: C17.1 R71.2 U1.22(TS2)
NetC15_2: C15.2 C16.2 C18.2 R61.2 U1.47(BAT)
NetC18_1: C18.1 U1.46(CP1)
NetC19_1: C19.1 U1.24(REG18)
NetC31_1: C31.1 U1.35(REG1)
NetC34_1: C34.1 Q19.2(E) U1.36(REGIN)
NetC36_1: C36.1 Q19.3(C) R96.1
NetD1_1: D1.1(K) Q1.1(G) R18.1
NetD2_1: D2.1(K) Q2.1(G) R20.1
NetD3_1: D3.1(K) Q3.1(G) R22.1
NetD4_1: D4.1(K) Q4.1(G) R24.1
NetD5_1: D5.1(K) Q5.1(G) R26.1
NetD6_1: D6.1(K) Q6.1(G) R28.1
NetD7_1: D7.1(K) Q7.1(G) R30.1
NetD8_1: D8.1(K) Q8.1(G) R32.1
NetD11_1: D11.1(K) R61.1
NetD12_1: D12.1(K) Q9.1(G) R51.1
NetD13_1: D13.1(K) Q10.1(G) R53.1
NetD14_1: D14.1(K) Q11.1(G) R55.1
NetD15_1: D15.1(K) Q12.1(G) R57.1
NetD16_1: D16.1(K) Q13.1(G) R59.1
NetD17_1: D17.1(K) Q14.1(G) R79.1
NetD18_1: D18.1(K) Q15.1(G) R81.1
NetD19_1: D19.1(K) Q16.1(G) R83.1
NetD20_1: D20.1(K) R96.2
NetQ1_3: Q1.3(D) R1.2 R2.2
NetQ2_3: Q2.3(D) R3.2 R4.2
NetQ3_3: Q3.3(D) R5.2 R6.2
NetQ4_3: Q4.3(D) R7.2 R8.2
NetQ5_3: Q5.3(D) R9.2 R10.2
NetQ6_3: Q6.3(D) R11.2 R12.2
NetQ7_3: Q7.3(D) R13.2 R14.2
NetQ8_3: Q8.3(D) R15.2 R16.2
NetQ9_3: Q9.3(D) R36.2 R37.2
NetQ10_3: Q10.3(D) R38.2 R39.2
NetQ11_3: Q11.3(D) R40.2 R41.2
NetQ12_3: Q12.3(D) R42.2 R43.2
NetQ13_3: Q13.3(D) R44.2 R45.2
NetQ14_3: Q14.3(D) R73.2 R74.2
NetQ15_3: Q15.3(D) R75.2 R76.2
NetQ16_3: Q16.3(D) R77.2 R78.2
NetQ17_1: Q17.1(G) R93.2 R94.1
NetQ17_3: Q17.3(D) R86.2
NetQ18_3: Q18.3(D) R93.1
NetQ19_1: Q19.1(B) R95.2
NetR62_2: R62.2 R64.2 U1.8(VC8)
NetR63_2: R63.2 R66.2 U1.6(VC10)
NetR65_1: R65.1 R67.2 U1.10(VC6)
NetR68_1: R68.1 U1.7(VC9)
NetR69_1: R69.1 U1.11(VC5)
NetR70_1: R70.1 U1.9(VC7)
NetR71_1: R71.1 S1.1
NetR89_2: R89.2 U1.26(SCL)
NetR90_2: R90.2 U1.27(SDA)
NetR95_1: R95.1 R177.1 U1.37(BREG)

Not connected (* = marked no-connect by the designer): U1 19(NC) 40(PCHG) 44(NC)

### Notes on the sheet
- N/A

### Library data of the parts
C1-C14 C20-C22 = CMP-0007145-4: CAP, CERM, 0.22 uF, 50 V, +/- 10%, X7R, AEC-Q200 Grade 1, 0603; Manufacturer: MuRata; Polarized: N; Value: 0.22uF; U/M: EA; Cap_F: 220nF; Value1: Unknown; VDC_V: 50V; TaMin_C: -55°C; TaMax_C: 125°C; Cap_Case: 0603; SizeArea_mm2: 1.28; SizeAreaWB_mm2: 4.68; SizeX_mm: 1.6; SizeY_mm: 0.8; SizeZ_mm: 1; AEC Category: Q200; AEC Qualified: Y
C15 = CMP-0008804-2: CAP, CERM, 2.2 uF, 100 V, +/- 10%, X7R, 1206_190; Manufacturer: Samsung Electro-Mechanics; Polarized: N; Value: 2.2uF; U/M: EA; Cap_F: 2.2µF; Value1: Unknown; VDC_V: 100V; TaMin_C: -55°C; TaMax_C: 125°C; Cap_Case: 1206; SizeArea_mm2: 5.12; SizeAreaWB_mm2: 10.92; SizeX_mm: 3.2; SizeY_mm: 1.6; SizeZ_mm: 1.9; AEC Category: Q200
C16 C17 C24 C25 C33 = CMP-0007237-4: CAP, CERM, 100 pF, 100 V, +/- 5%, C0G/NP0, 0603; Manufacturer: MuRata; Polarized: N; Value: 100pF; U/M: EA; Value1: Unknown; VDC_V: 100V; TaMin_C: -55°C; TaMax_C: 125°C; Cap_Case: 0603; SizeArea_mm2: 1.28; SizeAreaWB_mm2: 4.68; SizeX_mm: 1.6; SizeY_mm: 0.8; SizeZ_mm: 1; AEC Category: Q200
C18 = CMP-0007040-4: CAP, CERM, 1 uF, 25 V, +/- 10%, X7R, 0603; Manufacturer: TDK; Polarized: N; Value: 1uF; U/M: EA; Cap_F: 1µF; Value1: Unknown; VDC_V: 25V; TaMin_C: -55°C; TaMax_C: 125°C; Cap_Case: 0603; SizeArea_mm2: 1.28; SizeAreaWB_mm2: 4.68; SizeX_mm: 1.6; SizeY_mm: 0.8; SizeZ_mm: 1; AEC Category: Q200
C19 = CMP-0064934-4: CAP, CERM, 2.2 uF, 16 V,+/- 10%, X7R, 0603; Manufacturer: Taiyo Yuden; Polarized: N; Value: 2.2uF; U/M: EA; Cap_F: 2.2µF; Value1: Unknown; VDC_V: 16V; TaMin_C: -55°C; TaMax_C: 125°C; Cap_Case: 0603; SizeArea_mm2: 1.28; SizeAreaWB_mm2: 4.68; SizeX_mm: 1.6; SizeY_mm: 0.8; SizeZ_mm: 1; AEC Category: Q200
C23 C26 C32 C35 = CMP-0007455-4: CAP, CERM, 470 pF, 50 V, +/- 10%, X7R, 0603; Manufacturer: MuRata; Polarized: N; Value: 470pF; U/M: EA; Value1: Unknown; VDC_V: 50V; TaMin_C: -55°C; TaMax_C: 125°C; Cap_Case: 0603; SizeArea_mm2: 1.28; SizeAreaWB_mm2: 4.68; SizeX_mm: 1.6; SizeY_mm: 0.8; SizeZ_mm: 1; AEC Category: Q200
C27-C29 = CMP-0007434-4: CAP, CERM, 0.1 uF, 50 V, +/- 10%, X7R, 0603; Manufacturer: MuRata; Polarized: N; Value: 0.1uF; U/M: EA; Cap_F: 100nF; Value1: Unknown; VDC_V: 50V; TaMin_C: -55°C; TaMax_C: 125°C; Cap_Case: 0603; SizeArea_mm2: 1.28; SizeAreaWB_mm2: 4.68; SizeX_mm: 1.6; SizeY_mm: 0.8; SizeZ_mm: 1; AEC Category: Q200
C30 C31 = CMP-0007136-5: CAP, CERM, 1 uF, 16 V, +/- 10%, X7R, AEC-Q200 Grade 1, 0603; Manufacturer: MuRata; Polarized: N; Value: 1uF; U/M: EA; Cap_F: 1µF; Value1: Unknown; VDC_V: 16V; TaMin_C: -55°C; TaMax_C: 125°C; Cap_Case: 0603; SizeArea_mm2: 1.28; SizeAreaWB_mm2: 4.68; SizeX_mm: 1.6; SizeY_mm: 0.8; SizeZ_mm: 1; AEC Category: Q200; AEC Qualified: Y
C34 = CMP-0007444-4: CAP, CERM, 0.022 uF, 50 V, +/- 10%, X7R, 0603; Manufacturer: MuRata; Polarized: N; U/M: EA; Cap_F: 22nF; Value1: Unknown; VDC_V: 50V; TaMin_C: -55°C; TaMax_C: 125°C; Cap_Case: 0603; SizeArea_mm2: 1.28; SizeAreaWB_mm2: 4.68; SizeX_mm: 1.6; SizeY_mm: 0.8; SizeZ_mm: 1; AEC Category: Q200
C36 = CMP-0008710-2: CAP, CERM, 1 uF, 100 V, +/- 10%, X7R, 1206; Manufacturer: TDK; Polarized: N; Value: 1uF; U/M: EA; Cap_F: 1µF; ESR_ohm: 4.575m; Value1: 0.004575 ohm; VDC_V: 100V; IRMS_A: 3.3964A; TaMin_C: -55°C; TaMax_C: 125°C; SizeArea_mm2: 5.12; SizeAreaWB_mm2: 10.92; SizeX_mm: 3.2; SizeY_mm: 1.6; SizeZ_mm: 1.8; AEC Category: Q200
D1-D8 D12-D19 = CMP-0005900-4: Diode, Zener, 5.6 V, 300 mW, SOD-523; Manufacturer: Diodes Inc.; Power_W: 300mW; Value1: 0.3W; RJA_CperW: 417; SizeAreaWB_mm2: 5.13; SizeArea_mm2: 1.53; SizeX_mm: 1.7; SizeY_mm: 0.9; SizeZ_mm: 0.65; AEC Category: Q101
D9 = CMP-0028447-2: Diode, Schottky, 30 V, 0.2 A, SOD-323; Manufacturer: Diodes Inc.; Vf_V: 1V; Value: 30V; Value1: 0.2A; Io_A: 200mA; SizeAreaWB_mm2: 8.695; SizeArea_mm2: 3.645; SizeX_mm: 2.7; SizeY_mm: 1.35; SizeZ_mm: 1; AEC Category: Q101; Green_Lifecycle: Not Set; Green_REACh: Incomplete
D10 = CMP-0005782-3: Diode, Zener, 3.6 V, 500 mW, SOD-123; Manufacturer: ON Semiconductor; Power_W: 500mW; Value1: 0.5W; RJA_CperW: 340; SizeAreaWB_mm2: 13.095; SizeArea_mm2: 6.545; SizeX_mm: 3.85; SizeY_mm: 1.7; SizeZ_mm: 1.35; AEC Category: Q101
D11 D20 = CMP-0076979-3: Diode, Switching, 100 V, 0.25 A, SOD-523; Manufacturer: Nexperia; Vf_V: 1.25V; Value: 100V; Value1: 0.25A; Io_A: 250mA; TJmax_C: 150°C; SizeAreaWB_mm2: 5.13; SizeArea_mm2: 1.53; SizeX_mm: 1.7; SizeY_mm: 0.9; SizeZ_mm: 0.65; AEC Category: Q101; Green_Lifecycle: Not Set; Green_REACh: Incomplete
Q1-Q16 = CMP-0000211-1: MOSFET, N-CH, 20 V, 2.8 A, AEC-Q101, SOT-23; Manufacturer: Diodes Inc.; Alternate Manufacturer: None; U/M: EA; ChType: N; Value: 20V; Value1: 0; Rdson45_ohm: 90m; Value2: 1.4 nC; QgTyp_nC: 1.4; Vgs_V: 12V; IdsMax_A: 2.8A; SizeAreaWB_mm2: 14; SizeArea_mm2: 7.5; SizeX_mm: 2.5; SizeY_mm: 3; SizeZ_mm: 1.1; AEC Category: Q101; AEC Qualified: Y
Q17 = CMP-0000158-3: MOSFET, P-CH, -100 V, -0.6 A, SOT-23; Manufacturer: Diodes Inc.; Alternate Manufacturer: None; ChType: P; Value: -100V; Rdson45_ohm: 1; Value2: 3.5 nC; QgTyp_nC: 3.5; Vgs_V: -4V; IdsMax_A: -600mA; SizeAreaWB_mm2: 14; SizeArea_mm2: 7.5; SizeX_mm: 2.5; SizeY_mm: 3; SizeZ_mm: 1.1; AEC Category: Q101; ChMode: Enhancement
Q18 = CMP-0000947-2: MOSFET, N-CH, 100 V, 0.17 A, SOT-23; Manufacturer: Fairchild Semiconductor; Alternate Manufacturer: None; U/M: EA; ChType: N; Value: 100V; Value1: 1; Rdson45_ohm: 10; Value2: 1.8 nC; QgTyp_nC: 1.8; Vgs_V: 20V; IdsMax_A: 170mA; SizeAreaWB_mm2: 14; SizeArea_mm2: 7.5; SizeX_mm: 2.5; SizeY_mm: 3; SizeZ_mm: 1.1; AEC Category: Q101
Q19 = CMP-0000478-2: Transistor, NPN, 100 V, 3 A, AEC-Q101, SOT-23; Manufacturer: Diodes Inc.; CompType: BJT; PNP: 0; NPN: 1; Vceo_V: 100V; Vcesat1_V: 70mV; Value: 100 V; IcRated_A: 3A; Value1: 3 A; HfeMax: 300; TaMin_C: -55°C; TaMax_C: 150°C; SizeAreaWB_mm2: 14; SizeArea_mm2: 7.5; SizeX_mm: 2.5; SizeY_mm: 3; SizeZ_mm: 1.1; U/M: EA; AEC Category: Q101; AEC Qualified: Y
R1-R16 R36-R43 R45 R73-R78 = CMP-0017186-3: RES, 80.6, 1%, 0.25 W, AEC-Q200 Grade 0, 1206; Manufacturer: Vishay-Dale; Value: 80.6; Value_Code: 80R6; Power_W: 250mW; Value2: 0.25W; VDC_V: 200V; TempCo: 100 ppm/C; SizeArea_mm2: 5.12; SizeX_mm: 3.2; SizeY_mm: 1.6; SizeZ_mm: 1.35; EIA_Code: E96; AEC Category: Q200; AEC Qualified: Y; AEC Grade: 0
R17 R19 R21 R23 R25 R27 R29 R31 R33 R52 R54 R56 R58 R60 R61 R80 R82 R87-R90 R95 = CMP-0021991-4: RES, 100, 1%, 0.1 W, AEC-Q200 Grade 0, 0603; Manufacturer: Vishay-Dale; Value: 100; Value_Code: 100R; Power_W: 100mW; Value2: 0.1W; VDC_V: 75V; TempCo: 100 ppm/C; SizeArea_mm2: 1.28; SizeX_mm: 1.6; SizeY_mm: 0.8; SizeZ_mm: 1; EIA_Code: E96; AEC Category: Q200; AEC Qualified: Y; AEC Grade: 0
R18 R20 R22 R24 R26 R28 R30 R32 R51 R53 R55 R57 R59 R71 R79 R81 R83 R91 R92 = CMP-0025701-4: RES, 10 k, 5%, 0.1 W, AEC-Q200 Grade 0, 0603; Manufacturer: Vishay-Dale; Value: 10k; Value_Code: 10k0; Power_W: 100mW; Value2: 0.1W; VDC_V: 75V; TempCo: 200 ppm/C; SizeArea_mm2: 1.28; SizeX_mm: 1.6; SizeY_mm: 0.8; SizeZ_mm: 1; EIA_Code: E24; AEC Category: Q200; AEC Qualified: Y; AEC Grade: 0
R34 R46 R47 R72 = CMP-0026822-3: RES, 0, 5%, 0.063 W, AEC-Q200 Grade 0, 0402; Manufacturer: Vishay-Dale; Value: 0; Value_Code: 0000; Power_W: 63mW; Value2: 0.063W; VDC_V: 50V; TempCo: 200 ppm/C; SizeArea_mm2: 0.5; SizeX_mm: 1; SizeZ_mm: 0.6; EIA_Code: E24; AEC Category: Q200; AEC Qualified: Y
R35 R48-R50 R62-R70 = CMP-0025697-4: RES, 0, 5%, 0.1 W, AEC-Q200 Grade 0, 0603; Manufacturer: Vishay-Dale; Value: 0; Value_Code: 0000; Power_W: 100mW; Value2: 0.1W; VDC_V: 75V; TempCo: 200 ppm/C; SizeArea_mm2: 1.28; SizeX_mm: 1.6; SizeY_mm: 0.8; SizeZ_mm: 1; EIA_Code: E24; AEC Category: Q200; AEC Qualified: Y
R44 = CMP-0017186-3: RES, 80.6, 1%, 0.25 W, AEC-Q200 Grade 0, 1206; Manufacturer: Vishay-Dale; Value_Code: 80R6; Power_W: 250mW; Value2: 0.25W; VDC_V: 200V; TempCo: 100 ppm/C; SizeArea_mm2: 5.12; SizeX_mm: 3.2; SizeY_mm: 1.6; SizeZ_mm: 1.35; EIA_Code: E96; AEC Category: Q200; AEC Qualified: Y; AEC Grade: 0
R84 = CMP-0025754-2: RES, 20, 5%, 0.1 W, 0603; Manufacturer: Vishay-Dale; Power_W: 100mW; TempCo: 200 ppm/C; Value_Code: 20R0; U/M: EA; Value: 20; EIA_Code: E24; SizeX_mm: 1.6; SizeY_mm: 0.8; SizeZ_mm: 1; Value2: 0.1W; SizeArea_mm2: 1.28; VDC_V: 75V; AEC Category: Q200
R85 = CMP-0024664-3: RES, 13.3 k, 0.5%, 0.1 W, 0603; Manufacturer: Yageo America; Value: 13.3k; Value_Code: 13k3; Power_W: 100mW; Value2: 0.1W; VDC_V: 75V; TempCo: 50 ppm/C; SizeArea_mm2: 1.28; SizeX_mm: 1.6; SizeY_mm: 0.8; SizeZ_mm: 1; EIA_Code: E192; U/M: EA; AEC Category: Q200
R86 = CMP-0025495-3: RES, 665 k, 0.5%, 0.1 W, 0603; Manufacturer: Yageo America; Value: 665k; Power_W: 100mW; Value2: 0.1W; VDC_V: 75V; TempCo: 50 ppm/C; SizeArea_mm2: 1.28; SizeX_mm: 1.6; SizeY_mm: 0.8; SizeZ_mm: 1; EIA_Code: E192; U/M: EA; AEC Category: Q200
R93 = CMP-0025801-4: RES, 3.3 M, 5%, 0.1 W, AEC-Q200 Grade 0, 0603; Manufacturer: Vishay-Dale; Value: 3.3Meg; Value_Code: 3M30; Power_W: 100mW; Value2: 0.1W; VDC_V: 75V; TempCo: 200 ppm/C; SizeArea_mm2: 1.28; SizeX_mm: 1.6; SizeY_mm: 0.8; SizeZ_mm: 1; EIA_Code: E24; AEC Category: Q200; AEC Qualified: Y; AEC Grade: 0
R94 = CMP-0025736-4: RES, 1.0 M, 5%, 0.1 W, AEC-Q200 Grade 0, 0603; Manufacturer: Vishay-Dale; Value: 1.0Meg; Res_ohm: 1M; Value_Code: 1M00; Power_W: 100mW; Value2: 0.1W; VDC_V: 75V; TempCo: 200 ppm/C; SizeArea_mm2: 1.28; SizeX_mm: 1.6; SizeY_mm: 0.8; SizeZ_mm: 1; EIA_Code: E24; AEC Category: Q200; AEC Qualified: Y; AEC Grade: 0
R96 = CMP-0022942-5: RES, 249, 1%, 0.1 W, 0603; Manufacturer: Yageo; Value: 249; Value_Code: 249R; Power_W: 100mW; Value2: 0.1W; VDC_V: 75V; TempCo: 100 ppm/C; SizeArea_mm2: 1.28; SizeX_mm: 1.6; SizeY_mm: 0.8; SizeZ_mm: 1; EIA_Code: E96; AEC Category: Q200; AEC Qualified: N; SizeAreaWB_mm2: 4.68
R177 = CMP-0025702-2: RES, 10 M, 5%, 0.1 W, 0603; Manufacturer: Vishay-Dale; Power_W: 100mW; TempCo: 200 ppm/C; Value_Code: 10M0; U/M: EA; Value: 10Meg; EIA_Code: E24; SizeX_mm: 1.6; SizeY_mm: 0.8; SizeZ_mm: 1; Value2: 0.1W; SizeArea_mm2: 1.28; VDC_V: 75V; AEC Category: Q200
RT1-RT4 = 103AT-2: Thermistor NTC, 10.0k ohm, 1%, Disc, 5x8.4 mm; Manufacturer: Cantherm; Tolerance_%: 1; Power_W: 0.01; TaMin_C: -50; TaMax_C: 110; U/M: EA
S1 = CMP-0002210-1: Switch, Tactile, SPST-NO, 0.05A, 12V, SMD; Manufacturer: C&K Components; SwitchFunction: Off-Mom; PositionCount: 1; CurrentRating_mA: 50A
U1 = CMP-0084230-1: Multicell Battery Monitor and Protection Family, PFB0048A (TQFP-48); Alternate PartNumber: bq76952PFBT; Alternate Manufacturer: Texas Instruments; SizeAreaWB_mm2: 121; SizeZ_mm: 1.2; SizeX_mm: 9; SizeArea_mm2: 81; CompType: IC; AEC Qualified: N; AEC Category: Q200

## Sheet Aux power.SchDoc
size A3; Date: Not shown in title block; ApprovedBy: Not shown in title block; CheckedBy: Not shown in title block; Author: Not shown in title block; CompanyName: Not shown in title block; Engineer: Not shown in title block; Organization: Not shown in title block; Address1: Not shown in title block; Address2: Not shown in title block; Address3: Not shown in title block; Address4: Not shown in title block; DocumentNumber: 1; Revision: Use project parameter SCH_Rev; SheetNumber: 5; SheetTotal: 7; PageSetup: Record=PageOptions¦CenterHorizontal=True¦CenterVertical=True¦PrintScale=1.00¦XCorrection=1.00¦YCorrection=1.00¦PrintKind=0¦BorderSize=5000000¦LeftOffset=0¦BottomOffset=0¦Orientation=2¦PaperLength=1000¦PaperWidth=1000¦Scale=100¦PaperSource=15¦PrintQuality=600¦MediaType=1¦DitherType=10¦PaperKind=Letter¦PrintScaleMode=1
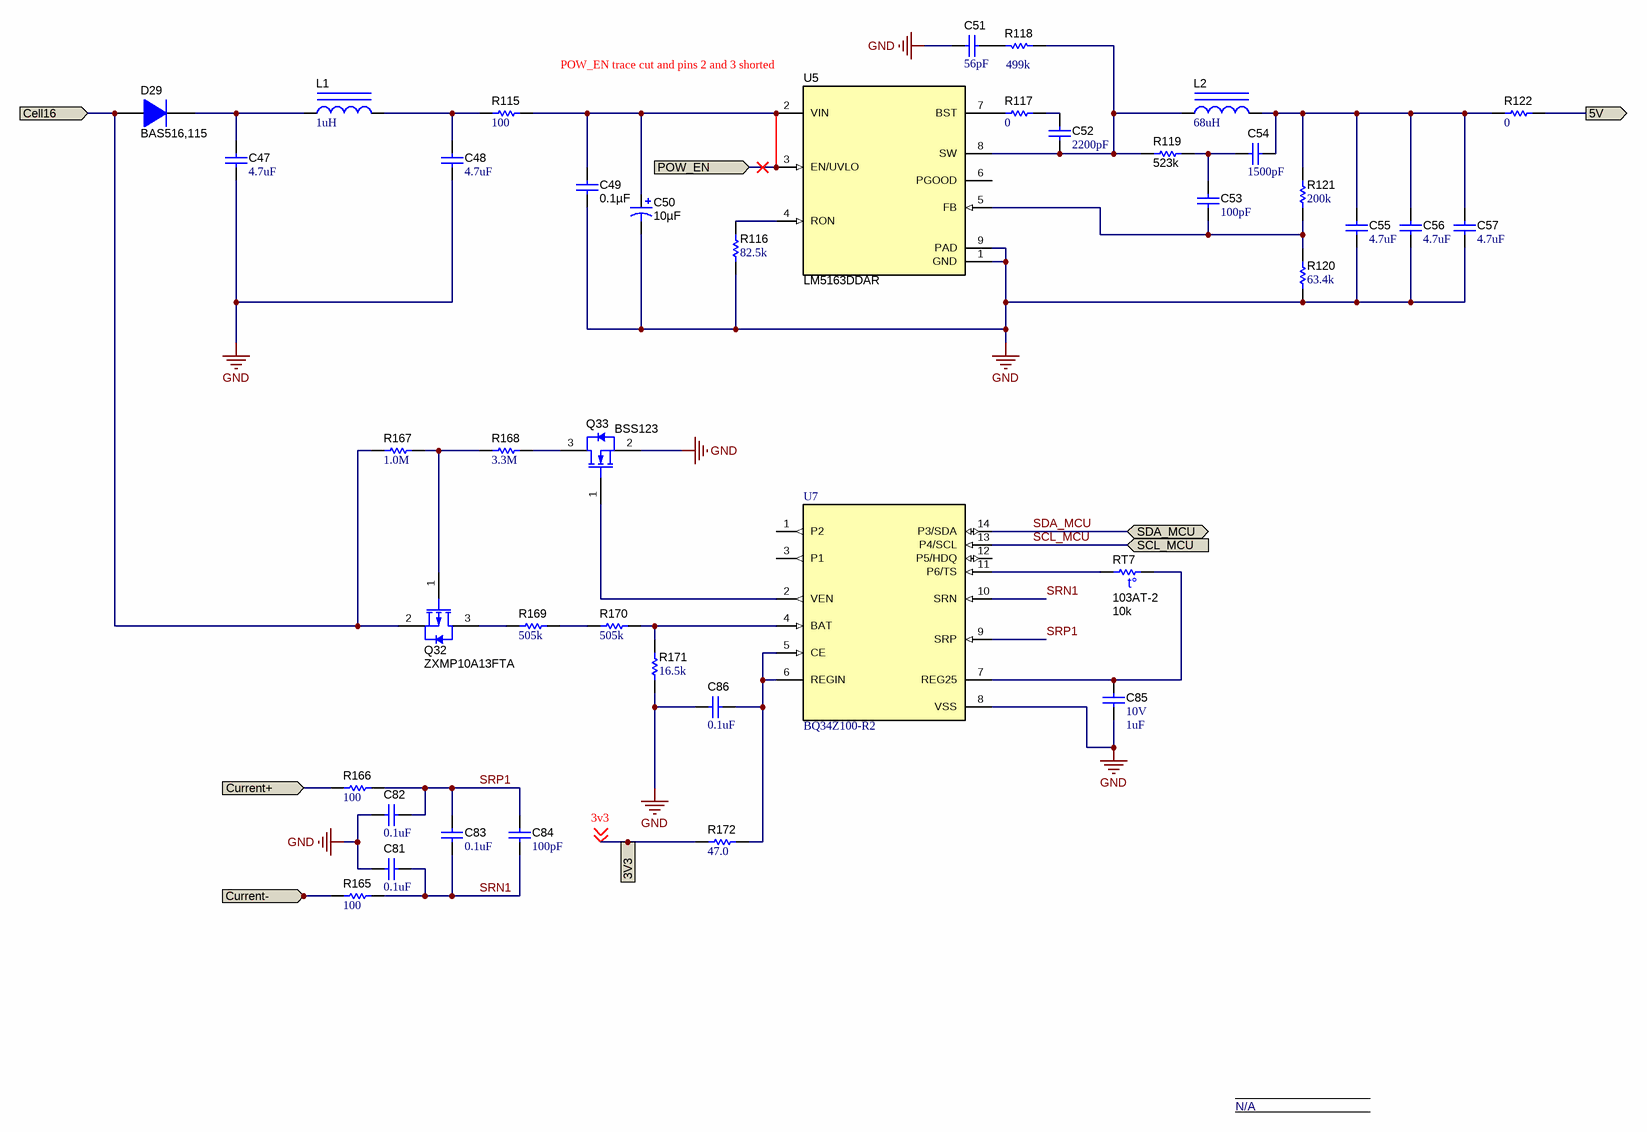
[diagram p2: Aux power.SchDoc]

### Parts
C47  ValueDisplayed: 4.7uF  [1210]  (hidden comment: C3225X7S2A475K200AE)
C48  ValueDisplayed: 4.7uF  [1210]  (hidden comment: C3225X7S2A475K200AE)
C49  ValueDisplayed: 0.1µF  [0603S]  (hidden comment: GRM188R72A104KA35D)
C50  ValueDisplayed: 10µF  [UUX_800x620]  (hidden comment: UUX2A100MNL1GS)
C51  ValueDisplayed: 56pF  [0603S]  (hidden comment: GRM1885C1H560JA01D)
C52  ValueDisplayed: 2200pF  [0402]  (hidden comment: GRM155R71H222KA01D)
C53  ValueDisplayed: 100pF  [0603S]  (hidden comment: GRM1885C1H101JA01D)
C54  ValueDisplayed: 1500pF  [0402]  (hidden comment: GRM155R71H152KA01D)
C55  ValueDisplayed: 4.7uF  [0805_HV]  (hidden comment: GRM21BR71C475KA73L)
C56  ValueDisplayed: 4.7uF  [0805_HV]  (hidden comment: GRM21BR71C475KA73L)
C57  ValueDisplayed: 4.7uF  [0805_HV]  (hidden comment: GRM21BR71C475KA73L)
C81  ValueDisplayed: 0.1uF  [0603S]  (hidden comment: GRM188R71H104KA93D)
C82  ValueDisplayed: 0.1uF  [0603S]  (hidden comment: GRM188R71H104KA93D)
C83  ValueDisplayed: 0.1uF  [0603S]  (hidden comment: GRM188R71H104KA93D)
C84  ValueDisplayed: 100pF  [0603S]  (hidden comment: GRM1885C2A101JA01D)
C85  VDC_V: 10V  ValueDisplayed: 1uF  [0603S]  (hidden comment: GRM185C81A105KE36D)
C86  ValueDisplayed: 0.1uF  [0603S]  (hidden comment: GRM188R71H104KA93D)
D29  BAS516,115  [SOD-523]
L1  ValueDisplayed: 1uH  [WE-MAPI_3015]  (hidden comment: 74438335010)
L2  ValueDisplayed: 68uH  [WE-PD_7345]  (hidden comment: 744777168)
Q32  ZXMP10A13FTA  [SOT-23]
Q33  BSS123  [SOT-23]
R115  ValueDisplayed: 100  [0603S]  (hidden comment: CRCW0603100RFKEA)
R116  ValueDisplayed: 82.5k  [0603S]  (hidden comment: CRCW060382K5FKEA)
R117  ValueDisplayed: 0  [0402]  (hidden comment: CRCW04020000Z0ED)
R118  ValueDisplayed: 499k  [0603S]  (hidden comment: RC0603FR-07499KL)
R119  ValueDisplayed: 523k  [0402]  (hidden comment: RC0402FR-07523KL)
R120  ValueDisplayed: 63.4k  [0603S]  (hidden comment: CRCW060363K4FKEA)
R121  ValueDisplayed: 200k  [0603S]  (hidden comment: CRCW0603200KFKEA)
R122  ValueDisplayed: 0  [0603S]  (hidden comment: CRCW06030000Z0EA)
R165  ValueDisplayed: 100  [0603S]  (hidden comment: CRCW0603100RFKEA)
R166  ValueDisplayed: 100  [0603S]  (hidden comment: CRCW0603100RFKEA)
R167  ValueDisplayed: 1.0M  [0603S]  (hidden comment: CRCW06031M00JNEA)
R168  ValueDisplayed: 3.3M  [0603S]  (hidden comment: CRCW06033M30JNEA)
R169  ValueDisplayed: 505k  [0603S]  (hidden comment: RT0603BRD07505KL)
R170  ValueDisplayed: 505k  [0603S]  (hidden comment: RT0603BRD07505KL)
R171  ValueDisplayed: 16.5k  [0603S]  (hidden comment: RT0603BRD0716K5L)
R172  ValueDisplayed: 47.0  [0603S]  (hidden comment: RC0603FR-0747RL)
RT7  103AT-2  value 10k  [THERMISTOR_103AT-2]
U5  LM5163DDAR  [DDA0008E_M]
U7  BQ34Z100-R2  [PW0014A_N]

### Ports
3V3 (out), 5V (out), Cell16 (in), Current+ (in), Current- (in), POW_EN (in), SCL_MCU (in), SDA_MCU (bidir)

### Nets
GND: C47.2 C48.2 C49.2 C50.2(-) C51.2 C55.2 C56.2 C57.2 C81.1 C82.1 C85.2 C86.2 Q33.2(S) R116.1 R120.1 R171.1 U5.1(GND) U5.9(PAD) U7.8(VSS)
3V3: R172.1 ; off-sheet 3v3, port 3V3
5V: R122.1 ; port 5V
BAT-: R166.1 ; port Current+
Cell16: D29.2(A) Q32.2(S) R167.1 ; port Cell16
PACK-: R165.1 ; port Current-
POW_EN: C49.1 C50.1(+) R115.2 U5.2(VIN) U5.3(EN/UVLO) ; port POW_EN
SCL_MCU: U7.13(P4/SCL) ; port SCL_MCU
SDA_MCU: U7.14(P3/SDA) ; port SDA_MCU
SRN1: C81.2 C83.2 C84.2 R165.2 U7.10(SRN)
SRP1: C82.2 C83.1 C84.1 R166.2 U7.9(SRP)
NetC47_1: C47.1 D29.1(K) L1.1
NetC48_1: C48.1 L1.2 R115.1
NetC51_1: C51.1 R118.1
NetC52_1: C52.1 R117.2
NetC52_2: C52.2 L2.1 R118.2 R119.1 U5.8(SW)
NetC53_1: C53.1 C54.2 R119.2
NetC53_2: C53.2 R120.2 R121.1 U5.5(FB)
NetC54_1: C54.1 C55.1 C56.1 C57.1 L2.2 R121.2 R122.2
NetC85_1: C85.1 RT7.2 U7.7(REG25)
NetC86_1: C86.1 R172.2 U7.5(CE) U7.6(REGIN)
NetQ32_1: Q32.1(G) R167.2 R168.1
NetQ32_3: Q32.3(D) R169.1
NetQ33_1: Q33.1(G) U7.2(VEN)
NetQ33_3: Q33.3(D) R168.2
NetR116_2: R116.2 U5.4(RON)
NetR117_1: R117.1 U5.7(BST)
NetR169_2: R169.2 R170.1
NetR170_2: R170.2 R171.2 U7.4(BAT)
NetRT7_1: RT7.1 U7.11(P6/TS)

Not connected (* = marked no-connect by the designer): U5 6(PGOOD); U7 1(P2) 3(P1) 12(P5/HDQ)

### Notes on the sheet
- POW_EN trace cut and pins 2 and 3 shorted
- N/A

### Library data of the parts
C47 C48 = CMP-0009135-2: CAP, CERM, 4.7 uF, 100 V, +/- 10%, X7S, 1210; Manufacturer: TDK; Polarized: N; Value: 4.7uF; U/M: EA; Cap_F: 4.7µF; Value1: Unknown; VDC_V: 100V; TaMin_C: -55°C; TaMax_C: 125°C; SizeArea_mm2: 8; SizeAreaWB_mm2: 14.7; SizeX_mm: 3.2; SizeY_mm: 2.5; SizeZ_mm: 1.35; AEC Category: Q200
C49 = GRM188R72A104KA35D: CAP, CERM, 0.1 µF, 100 V,+/- 10%, X7R, 0603; Manufacturer: MuRata; Polarized: N; CompType: Capacitor; Value: 0.1uF; U/M: EA; Cap_F: 0.0000001; Tolerance_%: 10; VDC_V: 100; Value2: 100V; TaMin_C: -55; TaMax_C: 125; Cap_Case: 0603; SizeArea_mm2: 1.28; SizeAreaWB_mm2: 4.68; SizeX_mm: 1.6; SizeY_mm: 0.8; SizeZ_mm: 1; AEC Category: Q200; Green_Lifecycle: Active; Green_REACh: Passed
C50 = UUX2A4R7MCL1GS: CAP, AL, 10 µF, 100 V, +/- 20%, SMD; Manufacturer: Nichicon; Polarized: Y; CompType: Capacitor; Value: 10uF; U/M: EA; Cap_F: 0.0000047; Tolerance_%: 20; VDC_V: 100; Value2: 100V; IRMS_A: 0.042; TaMin_C: -55; TaMax_C: 105; Cap_Case: 8x6.2mm; SizeAreaWB_mm2: 106.09; SizeArea_mm2: 68.89; SizeX_mm: 8.3; SizeZ_mm: 6.5; AEC Category: Q200; AEC Qualified: N
C51 = CMP-0007224-4: CAP, CERM, 56 pF, 50 V, +/- 5%, C0G/NP0, 0603; Manufacturer: MuRata; Polarized: N; Value: 56pF; U/M: EA; Value1: Unknown; VDC_V: 50V; TaMin_C: -55°C; TaMax_C: 125°C; Cap_Case: 0603; SizeArea_mm2: 1.28; SizeAreaWB_mm2: 4.68; SizeX_mm: 1.6; SizeY_mm: 0.8; SizeZ_mm: 1; AEC Category: Q200
C52 = CMP-0006683-2: CAP, CERM, 2200 pF, 50 V, +/- 10%, X7R, 0402; Manufacturer: MuRata; Polarized: N; Value: 2200pF; U/M: EA; Cap_F: 2.2nF; Value1: Unknown; VDC_V: 50V; TaMin_C: -55°C; TaMax_C: 125°C; SizeArea_mm2: 0.5; SizeAreaWB_mm2: 3; SizeX_mm: 1; SizeZ_mm: 0.6; AEC Category: Q200
C53 = CMP-0007171-4: CAP, CERM, 100 pF, 50 V, +/- 5%, C0G/NP0, 0603; Manufacturer: MuRata; Polarized: N; Value: 100pF; U/M: EA; Value1: Unknown; VDC_V: 50V; TaMin_C: -55°C; TaMax_C: 125°C; Cap_Case: 0603; SizeArea_mm2: 1.28; SizeAreaWB_mm2: 4.68; SizeX_mm: 1.6; SizeY_mm: 0.8; SizeZ_mm: 1; AEC Category: Q200
C54 = CMP-0006678-2: CAP, CERM, 1500 pF, 50 V, +/- 10%, X7R, 0402; Manufacturer: MuRata; Polarized: N; Value: 1500pF; U/M: EA; Cap_F: 1.5nF; Value1: Unknown; VDC_V: 50V; TaMin_C: -55°C; TaMax_C: 125°C; SizeArea_mm2: 0.5; SizeAreaWB_mm2: 3; SizeX_mm: 1; SizeZ_mm: 0.6; AEC Category: Q200
C55-C57 = CMP-0008334-2: CAP, CERM, 4.7 uF, 16 V, +/- 10%, X7R, 0805; Manufacturer: MuRata; Polarized: N; Value: 4.7uF; U/M: EA; Cap_F: 4.7µF; ESR_ohm: 6m; Value1: 0.006 ohm; VDC_V: 16V; TaMin_C: -55°C; TaMax_C: 125°C; Cap_Case: 0805; SizeArea_mm2: 2.5; SizeAreaWB_mm2: 6.75; SizeX_mm: 2; SizeY_mm: 1.25; SizeZ_mm: 1.45; AEC Category: Q200
C81-C83 C86 = CMP-0007434-4: as C27 on sheet Monitor and Cell balancing
C84 = CMP-0007237-4: as C16 on sheet Monitor and Cell balancing
C85 = CMP-0007152-2: CAP, CERM, 1 uF, 10 V, +/- 10%, X6S, 0603; Manufacturer: MuRata; TaMin_C: -55°C; Polarized: N; SizeAreaWB_mm2: 4.68; Value1: Unknown; U/M: EA; Value: 1uF; TaMax_C: 105°C; SizeZ_mm: 1; SizeX_mm: 1.6; SizeY_mm: 0.8; Cap_Case: 0603; SizeArea_mm2: 1.28; Cap_F: 1µF; AEC Category: Q200
D29 = CMP-0076979-3: as D11 on sheet Monitor and Cell balancing
L1 = CMP-0064154-1: Inductor, Shielded, 1 uH, 2.7 A, 0.039 ohm, SMD; Manufacturer: Wurth Elektronik; Value: 1uH; Ind_H: 1µH; Imax_A: 2.7A; Irms: 2.7A @ 40C rise; Isat: 4.5A @ 20% inductance drop; DCR_ohm: 39m; SizeAreaWB_mm2: 16; SizeArea_mm2: 9; SizeX_mm: 3; SizeZ_mm: 1.2; AEC Category: Q200; Green_Lifecycle: Active; Green_REACh: Passed
L2 = CMP-0064631-2: Inductor, Shielded Drum Core, Metal Composite, 68 uH, 0.87 A, 0.239 ohm, SMD; Manufacturer: Wurth Elektronik; Value: 68uH; Ind_H: 68µH; Imax_A: 870mA; Irms: 0.87A @ 40C rise; Isat: 0.95A @ 10% inductance drop; DCR_ohm: 0.239; Value2: 0.87A; SizeAreaWB_mm2: 86.49; SizeArea_mm2: 53.29; SizeX_mm: 7.3; SizeZ_mm: 4.5; AEC Category: Q200; Green_Lifecycle: Active; Green_REACh: Passed
Q32 = CMP-0000158-3: as Q17 on sheet Monitor and Cell balancing
Q33 = CMP-0000947-2: as Q18 on sheet Monitor and Cell balancing
R115 R165 R166 = CMP-0021991-4: as R17 on sheet Monitor and Cell balancing
R116 = CMP-0022620-4: RES, 82.5 k, 1%, 0.1 W, AEC-Q200 Grade 0, 0603; Manufacturer: Vishay-Dale; Value: 82.5k; Value_Code: 82k5; Power_W: 100mW; Value2: 0.1W; VDC_V: 75V; TempCo: 100 ppm/C; SizeArea_mm2: 1.28; SizeX_mm: 1.6; SizeY_mm: 0.8; SizeZ_mm: 1; EIA_Code: E96; AEC Category: Q200; AEC Qualified: Y; AEC Grade: 0
R117 = CMP-0026822-3: as R34 on sheet Monitor and Cell balancing
R118 = CMP-0023140-4: RES, 499 k, 1%, 0.1 W, 0603; Manufacturer: Yageo; Value: 499k; Power_W: 100mW; Value2: 0.1W; VDC_V: 75V; TempCo: 100 ppm/C; SizeArea_mm2: 1.28; SizeX_mm: 1.6; SizeY_mm: 0.8; SizeZ_mm: 1; EIA_Code: E96; AEC Category: Q200; AEC Qualified: N; SizeAreaWB_mm2: 4.68
R119 = CRCW0402523KFKED: RES, 523 k, 1%, 0.063 W, 0402; Manufacturer: Yageo; CompType: Resistor; Value: 523k; Res_ohm: 523000; Tolerance_%: 1; Power_W: 0.063; Value2: 0.063W; VDC_V: 50; TempCo: 100 ppm/C; SizeArea_mm2: 0.5; SizeZ_mm: 0.6; EIA_Code: E96; U/M: EA; AEC Category: Q200
R120 = CMP-0022540-4: RES, 63.4 k, 1%, 0.1 W, AEC-Q200 Grade 0, 0603; Manufacturer: Vishay-Dale; Value: 63.4k; Value_Code: 63k4; Power_W: 100mW; Value2: 0.1W; VDC_V: 75V; TempCo: 100 ppm/C; SizeArea_mm2: 1.28; SizeX_mm: 1.6; SizeY_mm: 0.8; SizeZ_mm: 1; EIA_Code: E96; AEC Category: Q200; AEC Qualified: Y; AEC Grade: 0
R121 = CMP-0022200-4: RES, 200 k, 1%, 0.1 W, AEC-Q200 Grade 0, 0603; Manufacturer: Vishay-Dale; Value: 200k; Power_W: 100mW; Value2: 0.1W; VDC_V: 75V; TempCo: 100 ppm/C; SizeArea_mm2: 1.28; SizeX_mm: 1.6; SizeY_mm: 0.8; SizeZ_mm: 1; EIA_Code: E96; AEC Category: Q200; AEC Qualified: Y; AEC Grade: 0
R122 = CMP-0025697-4: as R35 on sheet Monitor and Cell balancing
R167 = CMP-0025736-4: as R94 on sheet Monitor and Cell balancing
R168 = CMP-0025801-4: as R93 on sheet Monitor and Cell balancing
R169 R170 = CMP-0024305-2: RES, 505 k, 0.1%, 0.1 W, 0603; Manufacturer: Yageo America; Value: 505k; Power_W: 100mW; Value2: 0.1W; VDC_V: 75V; TempCo: 25 ppm/C; SizeArea_mm2: 1.28; SizeX_mm: 1.6; SizeY_mm: 0.8; SizeZ_mm: 1; EIA_Code: E192; U/M: EA; AEC Category: Q200
R171 = CMP-0023800-3: RES, 16.5 k, 0.1%, 0.1 W, 0603; Manufacturer: Yageo America; Value: 16.5k; Value_Code: 16k5; Power_W: 100mW; Value2: 0.1W; VDC_V: 75V; TempCo: 25 ppm/C; SizeArea_mm2: 1.28; SizeX_mm: 1.6; SizeY_mm: 0.8; SizeZ_mm: 1; EIA_Code: E192; U/M: EA; AEC Category: Q200
R172 = CMP-0023135-5: RES, 47.0, 1%, 0.1 W, 0603; Manufacturer: Yageo; Value: 47.0; Res_ohm: 47; Value_Code: 47R0; Power_W: 100mW; Value2: 0.1W; VDC_V: 75V; TempCo: 100 ppm/C; SizeArea_mm2: 1.28; SizeX_mm: 1.6; SizeY_mm: 0.8; SizeZ_mm: 1; AEC Category: Q200; AEC Qualified: N; SizeAreaWB_mm2: 4.68
RT7 = CMP-0002341-2: Thermistor NTC, 10.0k ohm, 1%, Disc, 5x8.4 mm; Manufacturer: SEMITEC Corporation; TaMax_C: 110°C; TaMin_C: -50°C; Power_W: 10mW; U/M: EA
U5 = CMP-0861029-1: 100-V Input, 0.5-A Synchronous Buck DC/DC Converter with Ultra-low IQ, DDA0008E (HSOIC-8); Alternate Manufacturer: Texas Instruments; SizeAreaWB_mm2: 55.2; SizeZ_mm: 1.7; SizeX_mm: 6; AEC Qualified: N; AEC Category: Q200; SizeArea_mm2: 29.4; CompType: IC; SizeY_mm: 4.9
U7 = CMP-0082026-1: Multi-Chemistry Impedance Track Standalone Fuel Gauge; Alternate Manufacturer: Texas Instruments; SizeAreaWB_mm2: 58.8; SizeZ_mm: 1.2; SizeX_mm: 6.4; SizeY_mm: 5; SizeArea_mm2: 32; CompType: IC; AEC Qualified: N; AEC Category: Q200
